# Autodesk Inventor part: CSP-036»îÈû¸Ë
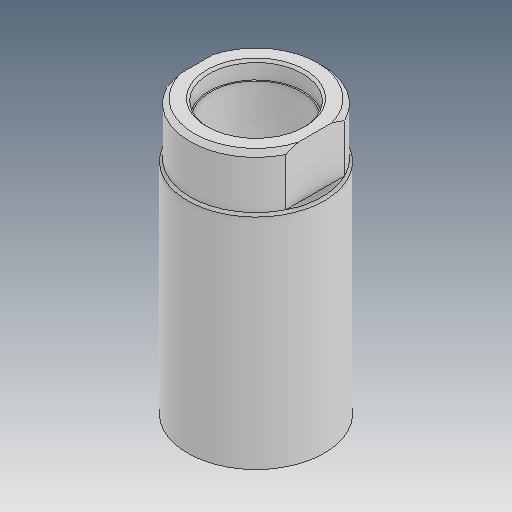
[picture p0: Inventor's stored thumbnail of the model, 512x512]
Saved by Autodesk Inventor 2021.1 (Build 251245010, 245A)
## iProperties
Created: 2019-01
Part Number: CSP-036»îÈû¸Ë
Material: Ogólny
Document SubType Name: Modeling
Designer: user
Density: 1 g/cm^3
Appearance: Domyślna
Author: user
Revision Number: ÈÎºÎ
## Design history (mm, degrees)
feature "µ¹½Ç3"
node "Bryła1"
